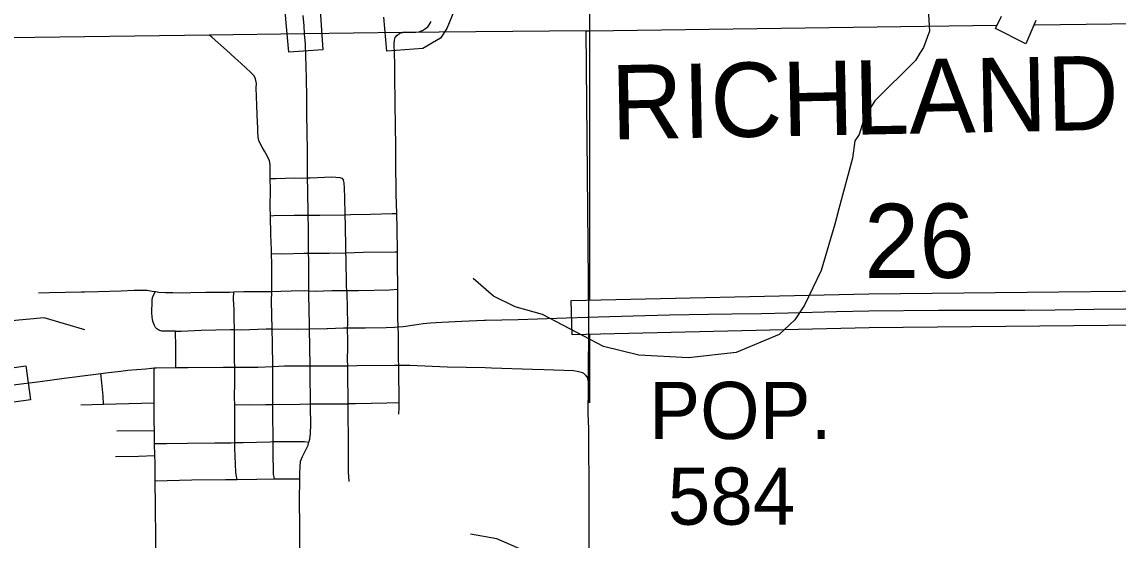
# Model space of a CAD drawing. Extents: x 10133 to 81668, y 7924 to 11018.
# Drawn here: x 11756.3 to 12044.1, y 9217.2 to 9353.2 of the extents above; entities that cross this region are included whole.
import ezdxf

# ---------------------------------------------------------------- set-up
doc = ezdxf.new("R2010")
doc.units = 0
for name, color, linetype in [('tdCoCityStreetMinor', 7, 'Continuous'), ('tdCoCoBndryTxt', 7, 'Continuous'), ('tdCoCorpPopTxt', 7, 'Continuous'), ('tdCoHydroRiver', 7, 'Continuous'), ('tdCoPriNonDiv', 7, 'Continuous'), ('tdCoRROwnerTxt', 7, 'Continuous'), ('tdCoSecRteBand', 7, 'Continuous'), ('tdCoSectNmbr', 7, 'Continuous'), ('tdCoStrucNonDivPri', 7, 'Continuous'), ('tdCoSurfGravel', 7, 'Continuous'), ('tdCoTwpBndryShd', 7, 'Continuous')]:
    doc.layers.add(name, color=color, linetype=linetype)

msp = doc.modelspace()

# ---------------------------------------------------------------- linework, layer by layer
at = {"layer": 'tdCoCityStreetMinor'}
for points in [[(11856.16, 9350.39), (11856.95, 9350.47), (11859.69, 9350.47), (11860.6, 9350.59), (11860.92, 9350.72), (11861.42, 9350.91), (11862.25, 9351.45), (11862.82, 9351.92), (11863.17, 9352.41), (11863.73, 9353.3)], [(11905.1, 9275.72), (11907.54, 9275.79), (11916.74, 9276.06), (11926.33, 9276.28), (11936.54, 9276.46), (11942.63, 9276.54), (11950.38, 9276.65), (11957.45, 9276.8), (11970.16, 9277.15), (11978.66, 9277.34), (11996.91, 9277.52), (12001.35, 9277.49), (12010.33, 9277.52), (12019.6, 9277.54), (12027.57, 9277.62), (12037.68, 9277.76), (12054.37, 9277.99)]]:
    msp.add_lwpolyline(points, dxfattribs=at)
at = {"layer": 'tdCoCorpPopTxt'}
for points in [[(11821.48, 9312.06), (11821.42, 9315.76), (11821.27, 9316.69), (11820.7, 9318.03), (11819.94, 9319.28), (11819.32, 9320.27), (11818.78, 9321.23), (11818.48, 9322.09), (11818.34, 9322.91), (11818.21, 9324.44), (11818.19, 9325.24), (11818.07, 9328.75), (11817.92, 9331.37), (11817.79, 9335.86), (11817.82, 9336.97), (11817.7, 9337.8), (11817.57, 9338.22), (11817.23, 9339.01), (11816.39, 9339.9), (11813.72, 9342.32), (11812.2, 9343.72), (11810, 9345.74), (11806.25, 9349.1), (11805.56, 9349.73)], [(11821.48, 9312.06), (11822.96, 9312.08), (11827.85, 9312.23), (11829.89, 9312.18), (11831.29, 9312.25), (11831.94, 9312.28), (11837.66, 9312.48), (11839.78, 9312.35), (11840.3, 9312.18), (11840.69, 9311.64)], [(11821.54, 9302.32), (11821.49, 9304.59), (11821.52, 9309.27), (11821.48, 9312.06)], [(11841.15, 9302.59), (11841.04, 9307.08), (11840.99, 9309.54), (11840.89, 9310.95), (11840.69, 9311.64)], [(11821.54, 9302.32), (11822.4, 9302.4), (11827.73, 9302.47), (11829.07, 9302.46), (11831.43, 9302.46), (11834.46, 9302.44), (11841.15, 9302.59)], [(11821.79, 9292.39), (11821.76, 9293.44), (11821.64, 9297.34), (11821.54, 9302.32)], [(11841.15, 9302.59), (11842.6, 9302.62), (11847.8, 9302.74), (11853.5, 9302.89), (11854.67, 9302.87)], [(11841.33, 9292.6), (11841.31, 9293.83), (11841.21, 9299.8), (11841.15, 9302.59)], [(11821.79, 9292.39), (11824.79, 9292.32), (11830.31, 9292.47), (11831.55, 9292.47), (11836.95, 9292.49), (11841.33, 9292.6)], [(11821.86, 9282.45), (11821.89, 9283.62), (11821.86, 9289.54), (11821.79, 9292.39)], [(11841.33, 9292.6), (11845.88, 9292.72), (11854.26, 9292.86), (11854.86, 9292.84)], [(11841.59, 9282.69), (11841.53, 9283.75), (11841.36, 9291.24), (11841.33, 9292.6)], [(11760.64, 9282.11), (11763.55, 9282.13), (11771.93, 9282.33), (11772.7, 9282.35), (11776.25, 9282.45), (11782.32, 9282.6), (11785.74, 9282.79), (11789.12, 9282.77), (11790.48, 9282.55), (11791.34, 9282.4)], [(11796.6, 9272.04), (11794.01, 9272.03), (11792.99, 9272.02), (11792.23, 9272.26), (11791.71, 9272.61), (11791.34, 9273), (11791.09, 9273.5), (11790.75, 9274.34), (11790.58, 9274.98), (11790.4, 9276.73), (11790.5, 9279.98), (11790.58, 9280.97), (11791.34, 9282.4)], [(11791.34, 9282.4), (11792.2, 9282.25), (11793.98, 9282.15), (11795.85, 9282.13), (11798.1, 9282.05), (11800.59, 9282.13), (11804.59, 9282.28), (11810.75, 9282.28), (11811.88, 9282.32)], [(11812.05, 9272.43), (11811.96, 9275.55), (11811.99, 9277.65), (11811.86, 9280.48), (11811.88, 9282.32)], [(11811.88, 9282.32), (11814.53, 9282.41), (11819.7, 9282.43), (11821.86, 9282.45)], [(11821.97, 9272.62), (11821.97, 9272.62), (11821.79, 9279.93), (11821.86, 9282.45)], [(11821.86, 9282.45), (11824.29, 9282.48), (11826.92, 9282.57), (11830.55, 9282.7), (11831.62, 9282.62), (11833.22, 9282.5), (11837.66, 9282.65), (11841.59, 9282.69)], [(11841.59, 9282.69), (11844.68, 9282.72), (11852.77, 9282.89), (11854.98, 9283.02)], [(11841.92, 9252.97), (11841.9, 9254.62), (11841.83, 9259.65), (11841.85, 9262.42), (11841.83, 9262.96), (11841.75, 9264.41), (11841.83, 9267.84), (11841.8, 9270.09), (11841.73, 9272.16), (11841.78, 9272.86), (11841.85, 9273.76), (11841.71, 9278.12), (11841.63, 9282), (11841.59, 9282.69)], [(11796.6, 9272.04), (11798.05, 9272.05), (11803.36, 9272.25), (11811, 9272.44), (11812.05, 9272.43)], [(11796.7, 9262.47), (11796.67, 9267.86), (11796.6, 9272.04)], [(11812.05, 9272.43), (11813.88, 9272.41), (11820.42, 9272.63), (11821.97, 9272.62)], [(11812.14, 9252.8), (11812.11, 9254.56), (11812.16, 9258.71), (11812.16, 9261.69), (11812.14, 9262.6), (11812.11, 9264.28), (11812.06, 9267.07), (11812.08, 9271.33), (11812.05, 9272.43)], [(11822.13, 9252.76), (11822.18, 9256.69), (11822.13, 9261.16), (11822.12, 9262.78), (11822.06, 9268.78), (11821.97, 9272.62)], [(11821.97, 9272.62), (11828.82, 9272.58), (11831.78, 9272.62)], [(11777.7, 9252.85), (11777.57, 9254.92), (11777.25, 9258.49), (11776.98, 9260.94)], [(11905.29, 9199.19), (11905.17, 9206.37), (11905.22, 9227.48), (11905.09, 9246.02), (11905.02, 9248.69), (11905.01, 9248.71), (11904.97, 9250.08), (11904.98, 9251.46), (11905, 9254.8), (11905.02, 9257.72), (11905.02, 9258.16)], [(11777.7, 9252.85), (11790.98, 9253.24)], [(11771.76, 9252.68), (11777.7, 9252.85)], [(11812.21, 9242.77), (11812.21, 9245.19), (11812.21, 9249.38), (11812.14, 9252.8)], [(11812.14, 9252.8), (11816.04, 9252.72), (11820.23, 9252.75), (11822.13, 9252.76)], [(11822.2, 9243.02), (11822.11, 9250.97), (11822.13, 9252.76)], [(11822.13, 9252.76), (11829.24, 9252.82), (11832.01, 9252.93), (11833.03, 9252.97), (11839.47, 9252.94), (11841.92, 9252.97)], [(11855.23, 9250.2), (11855.3, 9251.95), (11855.32, 9253.21), (11852.1, 9253.09), (11843.83, 9252.99), (11841.92, 9252.97)], [(11842.15, 9232.55), (11841.98, 9235.14), (11841.98, 9239.8), (11842.03, 9243.82), (11841.93, 9250.13), (11841.93, 9252.33), (11841.92, 9252.97)], [(11781.16, 9245.86), (11791.04, 9245.99)], [(11791.11, 9242.5), (11794.21, 9242.58), (11799.74, 9242.6), (11806.96, 9242.68), (11811.23, 9242.75), (11812.21, 9242.77)], [(11812.21, 9242.77), (11814.39, 9242.82), (11821.37, 9242.97), (11822.2, 9243.02)], [(11812.75, 9233.13), (11812.58, 9233.87), (11812.45, 9235.01), (11812.21, 9241.27), (11812.21, 9242.77)], [(11822.2, 9243.02), (11823.19, 9243.07), (11828.67, 9243.04), (11830.42, 9243.02), (11831.62, 9242.87)], [(11822.55, 9233.25), (11822.31, 9234.52), (11822.23, 9240.52), (11822.2, 9243.02)], [(11780.85, 9239.1), (11786.89, 9239.2), (11791.18, 9239.37)], [(11791.26, 9232.76), (11794.39, 9232.81), (11800.92, 9232.96), (11809.68, 9233.11), (11812.75, 9233.13)], [(11812.75, 9233.13), (11817.99, 9233.18), (11822.55, 9233.25)], [(11822.55, 9233.25), (11824.77, 9233.28), (11829.22, 9233.28)]]:
    msp.add_lwpolyline(points, dxfattribs=at)
at = {"layer": 'tdCoHydroRiver'}
for points in [[(11994.23, 9356.65), (11994.57, 9350.74), (11992.99, 9346.45), (11992.07, 9345.01), (11990.92, 9343.09), (11980.22, 9332.48), (11977.46, 9328.17), (11976.12, 9323.64), (11974.97, 9321.96), (11974.34, 9317.45), (11970.8, 9304.13), (11970.13, 9301.75), (11969.69, 9300.08), (11966.12, 9287.94), (11961.78, 9278.86), (11959.25, 9275.03), (11955.06, 9271.16), (11943.78, 9266.46), (11931.25, 9265.05), (11918.22, 9265.76), (11908.94, 9267.95), (11892.92, 9276.42), (11885.78, 9278.42), (11880.05, 9281.16), (11874.76, 9285.8)], [(11772.82, 9272.34), (11762.11, 9275.48), (11752.65, 9274.61)], [(11888.37, 9214.3), (11880.97, 9217.48), (11874.08, 9218.77)]]:
    msp.add_lwpolyline(points, dxfattribs=at)
at = {"layer": 'tdCoPriNonDiv'}
for points in [[(11833.31, 9374.4), (11835.29, 9345.87), (11826.31, 9345.27), (11824.74, 9362.69)], [(11871.97, 9361.5), (11867.83, 9351.43), (11866.13, 9348.87), (11861.56, 9346.19), (11852.11, 9345.49), (11851.26, 9354.45)], [(12022.45, 9353.59), (12019.9, 9347.44), (12011.86, 9351.46), (12013.45, 9354.65)], [(12095.23, 9274), (11978.74, 9272.85), (11900.74, 9271.09), (11900.47, 9280.08), (11978.62, 9281.84), (12095.11, 9283)], [(11713.94, 9256.71), (11757.29, 9262.91), (11758.54, 9254), (11711.55, 9247.46)]]:
    msp.add_lwpolyline(points, dxfattribs=at)
at = {"layer": 'tdCoSecRteBand'}
msp.add_lwpolyline([(11830.5, 9350.06), (11830.37, 9352.11), (11830.07, 9354.89)], dxfattribs=at)
at = {"layer": 'tdCoStrucNonDivPri'}
for points in [[(11905.28, 9385.73), (11905.25, 9350.86)], [(11905.25, 9350.86), (12012.27, 9352.28)], [(12022.22, 9352.42), (12055.93, 9352.87)], [(11904.44, 9350.85), (11905.25, 9350.86)], [(11905.25, 9350.86), (11905.27, 9280.21)], [(11905.27, 9271.21), (11905.28, 9253.22)]]:
    msp.add_lwpolyline(points, dxfattribs=at)
at = {"layer": 'tdCoSurfGravel'}
msp.add_lwpolyline([(11905.17, 9206.37), (11905.22, 9227.48), (11905.09, 9246.02), (11905, 9248.71), (11904.97, 9250.05), (11905.02, 9257.72), (11905.1, 9275.72), (11904.44, 9350.85), (11856.16, 9350.39), (11830.5, 9350.06), (11805.56, 9349.73), (11753.1, 9349.04), (11753.46, 9257.83), (11752.84, 9195.79)], dxfattribs=at)
at = {"layer": 'tdCoTwpBndryShd'}
for points in [[(11831.78, 9272.62), (11831.77, 9273.56), (11831.62, 9281.75), (11831.62, 9282.62), (11831.57, 9290.68), (11831.55, 9292.47), (11831.48, 9299.13), (11831.43, 9302.46), (11831.33, 9309.02), (11831.29, 9312.25), (11831.23, 9317.93), (11831.13, 9325.6), (11831.11, 9327.47), (11831.05, 9333.34), (11831.01, 9338.37), (11830.69, 9347.3), (11830.5, 9350.06)], [(11855.05, 9273.18), (11854.98, 9275.5), (11854.96, 9280.13), (11854.98, 9283.02), (11854.98, 9283.27), (11854.91, 9289.85), (11854.86, 9292.84), (11854.76, 9299), (11854.67, 9302.87), (11854.56, 9307.98), (11854.46, 9316.61), (11854.41, 9320.11), (11854.35, 9326.4), (11854.34, 9327.61), (11854.29, 9330.12), (11854.19, 9340.78), (11854.17, 9342.21), (11854.04, 9347.38), (11854.09, 9348.42), (11854.31, 9349.06), (11854.81, 9349.73), (11855.29, 9350.06), (11855.5, 9350.2), (11856.16, 9350.39)], [(11855.05, 9273.18), (11856.37, 9273.28), (11859.33, 9273.72), (11861.6, 9274.01), (11863.55, 9274.21), (11866.51, 9274.38), (11871.81, 9274.66), (11877.68, 9274.93), (11877.95, 9274.93), (11886.6, 9275.08), (11899.26, 9275.54), (11904.73, 9275.71), (11905.1, 9275.72)], [(11831.78, 9272.62), (11836.34, 9272.68), (11836.52, 9272.68), (11840.71, 9272.86), (11841.78, 9272.86), (11846.51, 9272.91), (11851.91, 9272.98), (11854.05, 9273.1), (11855.05, 9273.18)], [(11831.92, 9262.89), (11831.78, 9272.62)], [(11831.78, 9272.62), (11831.78, 9272.62)], [(11855.22, 9263.08), (11855.18, 9264.47), (11855.18, 9268.62), (11855.1, 9271.21), (11855.05, 9273.18)], [(11753.46, 9257.83), (11754, 9257.9), (11761.1, 9258.82), (11767.39, 9259.66), (11774.96, 9260.67), (11776.98, 9260.94), (11779, 9261.21), (11782.28, 9261.55), (11784.04, 9261.74), (11788.8, 9262.16), (11790.25, 9262.34), (11790.99, 9262.38)], [(11791.46, 9196.37), (11791.39, 9197.64), (11791.58, 9204.6), (11791.39, 9217.45), (11791.31, 9226.18), (11791.26, 9232.76), (11791.22, 9237.48), (11791.18, 9239.37), (11791.11, 9242.5), (11791.04, 9245.99), (11790.99, 9248.2), (11790.98, 9253.24), (11790.97, 9260.14), (11790.99, 9261.84), (11790.99, 9262.38)], [(11790.99, 9262.38), (11791.51, 9262.41), (11796.7, 9262.47), (11799.85, 9262.51), (11809.09, 9262.59), (11812.14, 9262.6), (11817.79, 9262.61), (11818.17, 9262.61), (11822.12, 9262.78), (11825.24, 9262.91), (11831.92, 9262.89)], [(11829.62, 9197.4), (11829.36, 9208.99), (11829.26, 9220.92), (11829.16, 9227.52), (11829.22, 9233.28), (11829.23, 9234.84), (11829.31, 9236.42), (11829.43, 9237.9), (11829.95, 9239.16), (11831.43, 9242.09), (11831.62, 9242.87), (11831.82, 9243.65), (11832.07, 9245.18), (11832.14, 9247.54), (11832.02, 9252.16), (11832.01, 9252.93), (11831.94, 9261.21), (11831.92, 9262.89)], [(11831.92, 9262.89), (11833.36, 9262.89), (11836.69, 9262.91), (11840.16, 9262.94), (11841.83, 9262.96), (11844.18, 9262.98), (11854.1, 9263.08), (11855.22, 9263.08)], [(11855.32, 9253.21), (11855.35, 9254.88), (11855.25, 9260.55), (11855.25, 9262.18), (11855.22, 9263.08)], [(11855.22, 9263.08), (11858.12, 9263.06), (11867.91, 9262.69), (11877.87, 9262.47), (11879.53, 9262.41), (11890.35, 9262.05), (11893.36, 9261.97), (11901.1, 9261.7), (11902.06, 9261.55), (11902.73, 9261.36), (11903.12, 9261.23), (11903.37, 9261.14), (11903.71, 9260.96), (11904.26, 9260.49), (11904.65, 9259.85), (11904.85, 9259.16), (11905.02, 9258.16)]]:
    msp.add_lwpolyline(points, dxfattribs=at)

# ---------------------------------------------------------------- texts
at = {"layer": 'tdCoCoBndryTxt'}
msp.add_text('RICHLAND', height=19.5, rotation=1.1197, dxfattribs=at).set_placement((11911.13, 9322.31))
at = {"layer": 'tdCoRROwnerTxt'}
msp.add_text('26', height=19.5, rotation=0.2308, dxfattribs=at).set_placement((11977.43, 9285.92))
at = {"layer": 'tdCoSectNmbr'}
for s, p in [('POP.', (11920.97, 9243.72)), ('584', (11925.85, 9221.22))]:
    msp.add_text(s, height=15, dxfattribs=at).set_placement(p)

doc.saveas('drawing.dxf')
